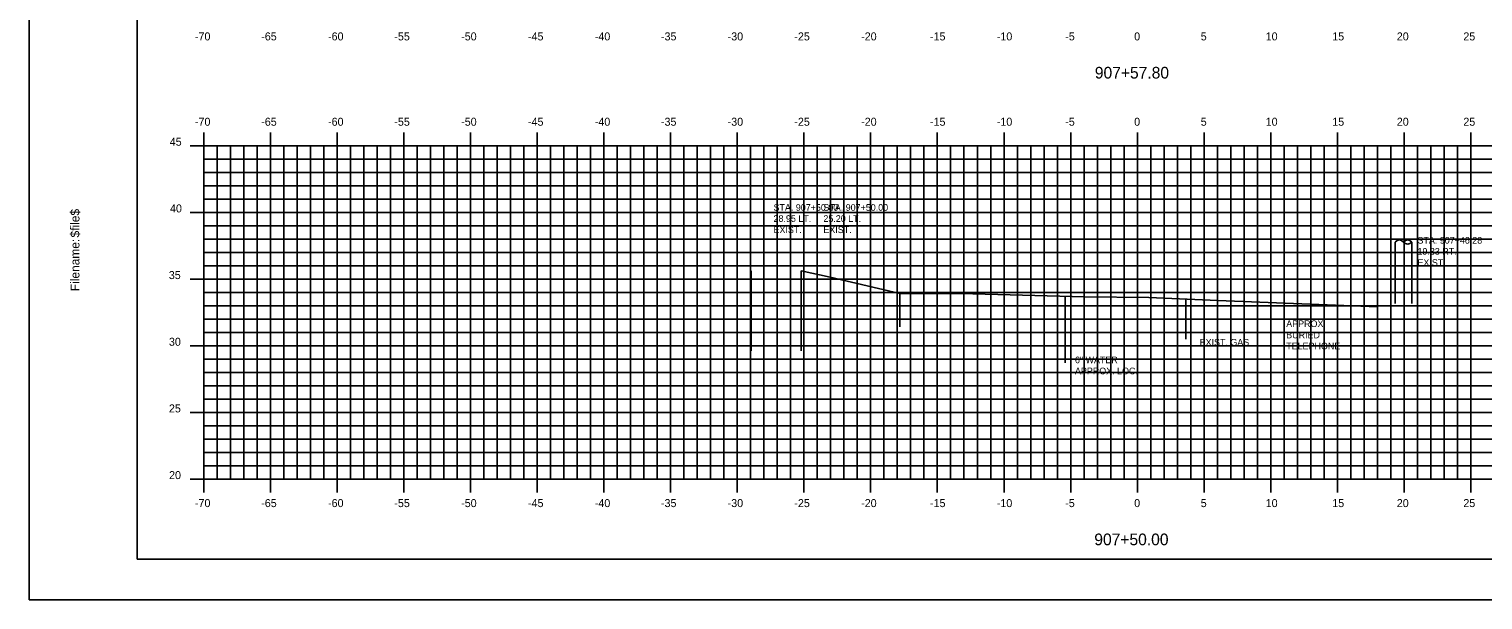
# Model space of a CAD drawing. Extents: x 1025909 to 1026079, y 394697 to 394807.
# Drawn here: x 1025908.6 to 1026017.6, y 394696.5 to 394739.4 of the extents above; entities that cross this region are included whole.
import ezdxf

# ---------------------------------------------------------------- set-up
doc = ezdxf.new("R2010")
doc.units = 0
for name, color, linetype in [('BORDER', 7, 'Continuous'), ('D_Text_Monospaced', 7, 'Continuous'), ('H_V ANNOTATION', 7, 'Continuous'), ('MAJOR', 7, 'Continuous'), ('MINOR', 7, 'Continuous'), ('PLOT BOUNDARY', 7, 'Continuous'), ('S_Roadway_Centerline', 7, 'Continuous'), ('S_Roadway_Edge_Pavement', 7, 'Continuous'), ('S_Utilities_Pole_Power', 7, 'Continuous'), ('S_Utilities_UG_Gas_Line', 7, 'Continuous'), ('S_Utilities_UG_Sanitary_Sewer', 7, 'Continuous'), ('S_Utilities_UG_Water_Line', 7, 'Continuous')]:
    doc.layers.add(name, color=color, linetype=linetype)

msp = doc.modelspace()

# ---------------------------------------------------------------- linework, layer by layer
at = {"layer": 'BORDER'}
for p, q in [((1025916.68, 394804.61), (1025916.68, 394699.61)), ((1025916.68, 394699.61), (1026076.68, 394699.61))]:
    msp.add_line(p, q, dxfattribs=at)
at = {"layer": 'MAJOR'}
for p, q in [((1025921.68, 394731.61), (1025921.68, 394730.61)), ((1025926.68, 394731.61), (1025926.68, 394730.61)), ((1025931.68, 394731.61), (1025931.68, 394730.61)), ((1025936.68, 394731.61), (1025936.68, 394730.61)), ((1025941.68, 394731.61), (1025941.68, 394730.61)), ((1025946.68, 394731.61), (1025946.68, 394730.61)), ((1025951.68, 394731.61), (1025951.68, 394730.61)), ((1025956.68, 394731.61), (1025956.68, 394730.61)), ((1025961.68, 394731.61), (1025961.68, 394730.61)), ((1025966.68, 394731.61), (1025966.68, 394730.61)), ((1025971.68, 394731.61), (1025971.68, 394730.61)), ((1025976.68, 394731.61), (1025976.68, 394730.61)), ((1025981.68, 394731.61), (1025981.68, 394730.61)), ((1025986.68, 394731.61), (1025986.68, 394730.61)), ((1025991.68, 394731.61), (1025991.68, 394730.61)), ((1025996.68, 394731.61), (1025996.68, 394730.61)), ((1026001.68, 394731.61), (1026001.68, 394730.61)), ((1026006.68, 394731.61), (1026006.68, 394730.61)), ((1026011.68, 394731.61), (1026011.68, 394730.61)), ((1026016.68, 394731.61), (1026016.68, 394730.61)), ((1025920.67, 394730.61), (1025921.68, 394730.61)), ((1025921.68, 394730.61), (1026061.68, 394730.61)), ((1025921.68, 394705.61), (1025921.68, 394730.61)), ((1025926.68, 394705.61), (1025926.68, 394730.61)), ((1025931.68, 394705.61), (1025931.68, 394730.61)), ((1025936.68, 394705.61), (1025936.68, 394730.61)), ((1025941.68, 394705.61), (1025941.68, 394730.61)), ((1025946.68, 394705.61), (1025946.68, 394730.61)), ((1025951.68, 394705.61), (1025951.68, 394730.61)), ((1025956.68, 394705.61), (1025956.68, 394730.61)), ((1025961.68, 394705.61), (1025961.68, 394730.61)), ((1025966.68, 394705.61), (1025966.68, 394730.61)), ((1025971.68, 394705.61), (1025971.68, 394730.61)), ((1025976.68, 394705.61), (1025976.68, 394730.61)), ((1025981.68, 394705.61), (1025981.68, 394730.61)), ((1025986.68, 394705.61), (1025986.68, 394730.61)), ((1025991.68, 394705.61), (1025991.68, 394730.61)), ((1025996.68, 394705.61), (1025996.68, 394730.61)), ((1026001.68, 394705.61), (1026001.68, 394730.61)), ((1026006.68, 394705.61), (1026006.68, 394730.61)), ((1026011.68, 394705.61), (1026011.68, 394730.61)), ((1026016.68, 394705.61), (1026016.68, 394730.61)), ((1025920.67, 394725.61), (1025921.68, 394725.61)), ((1025921.68, 394725.61), (1026061.68, 394725.61)), ((1025920.67, 394720.61), (1025921.68, 394720.61)), ((1025921.68, 394720.61), (1026061.68, 394720.61)), ((1025920.67, 394715.61), (1025921.68, 394715.61)), ((1025921.68, 394715.61), (1026061.68, 394715.61)), ((1025920.67, 394710.61), (1025921.68, 394710.61)), ((1025921.68, 394710.61), (1026061.68, 394710.61)), ((1025920.67, 394705.61), (1025921.68, 394705.61)), ((1025921.68, 394705.61), (1026061.68, 394705.61)), ((1025921.68, 394704.6), (1025921.68, 394705.61)), ((1025926.68, 394704.6), (1025926.68, 394705.61)), ((1025931.68, 394704.6), (1025931.68, 394705.61)), ((1025936.68, 394704.6), (1025936.68, 394705.61)), ((1025941.68, 394704.6), (1025941.68, 394705.61)), ((1025946.68, 394704.6), (1025946.68, 394705.61)), ((1025951.68, 394704.6), (1025951.68, 394705.61)), ((1025956.68, 394704.6), (1025956.68, 394705.61)), ((1025961.68, 394704.6), (1025961.68, 394705.61)), ((1025966.68, 394704.6), (1025966.68, 394705.61)), ((1025971.68, 394704.6), (1025971.68, 394705.61)), ((1025976.68, 394704.6), (1025976.68, 394705.61)), ((1025981.68, 394704.6), (1025981.68, 394705.61)), ((1025986.68, 394704.6), (1025986.68, 394705.61)), ((1025991.68, 394704.6), (1025991.68, 394705.61)), ((1025996.68, 394704.6), (1025996.68, 394705.61)), ((1026001.68, 394704.6), (1026001.68, 394705.61)), ((1026006.68, 394704.6), (1026006.68, 394705.61)), ((1026011.68, 394704.6), (1026011.68, 394705.61)), ((1026016.68, 394704.6), (1026016.68, 394705.61))]:
    msp.add_line(p, q, dxfattribs=at)
at = {"layer": 'MINOR'}
for p, q in [((1025922.68, 394705.61), (1025922.68, 394730.61)), ((1025923.68, 394705.61), (1025923.68, 394730.61)), ((1025924.68, 394705.61), (1025924.68, 394730.61)), ((1025925.68, 394705.61), (1025925.68, 394730.61)), ((1025927.68, 394705.61), (1025927.68, 394730.61)), ((1025928.68, 394705.61), (1025928.68, 394730.61)), ((1025929.68, 394705.61), (1025929.68, 394730.61)), ((1025930.68, 394705.61), (1025930.68, 394730.61)), ((1025932.68, 394705.61), (1025932.68, 394730.61)), ((1025933.68, 394705.61), (1025933.68, 394730.61)), ((1025934.68, 394705.61), (1025934.68, 394730.61)), ((1025935.68, 394705.61), (1025935.68, 394730.61)), ((1025937.68, 394705.61), (1025937.68, 394730.61)), ((1025938.68, 394705.61), (1025938.68, 394730.61)), ((1025939.68, 394705.61), (1025939.68, 394730.61)), ((1025940.68, 394705.61), (1025940.68, 394730.61)), ((1025942.68, 394705.61), (1025942.68, 394730.61)), ((1025943.68, 394705.61), (1025943.68, 394730.61)), ((1025944.68, 394705.61), (1025944.68, 394730.61)), ((1025945.68, 394705.61), (1025945.68, 394730.61)), ((1025947.68, 394705.61), (1025947.68, 394730.61)), ((1025948.68, 394705.61), (1025948.68, 394730.61)), ((1025949.68, 394705.61), (1025949.68, 394730.61)), ((1025950.68, 394705.61), (1025950.68, 394730.61)), ((1025952.68, 394705.61), (1025952.68, 394730.61)), ((1025953.68, 394705.61), (1025953.68, 394730.61)), ((1025954.68, 394705.61), (1025954.68, 394730.61)), ((1025955.68, 394705.61), (1025955.68, 394730.61)), ((1025957.68, 394705.61), (1025957.68, 394730.61)), ((1025958.68, 394705.61), (1025958.68, 394730.61)), ((1025959.68, 394705.61), (1025959.68, 394730.61)), ((1025960.68, 394705.61), (1025960.68, 394730.61)), ((1025962.68, 394705.61), (1025962.68, 394730.61)), ((1025963.68, 394705.61), (1025963.68, 394730.61)), ((1025964.68, 394705.61), (1025964.68, 394730.61)), ((1025965.68, 394705.61), (1025965.68, 394730.61)), ((1025967.68, 394705.61), (1025967.68, 394730.61)), ((1025968.68, 394705.61), (1025968.68, 394730.61)), ((1025969.68, 394705.61), (1025969.68, 394730.61)), ((1025970.68, 394705.61), (1025970.68, 394730.61)), ((1025972.68, 394705.61), (1025972.68, 394730.61)), ((1025973.68, 394705.61), (1025973.68, 394730.61)), ((1025974.68, 394705.61), (1025974.68, 394730.61)), ((1025975.68, 394705.61), (1025975.68, 394730.61)), ((1025977.68, 394705.61), (1025977.68, 394730.61)), ((1025978.68, 394705.61), (1025978.68, 394730.61)), ((1025979.68, 394705.61), (1025979.68, 394730.61)), ((1025980.68, 394705.61), (1025980.68, 394730.61)), ((1025982.68, 394705.61), (1025982.68, 394730.61)), ((1025983.68, 394705.61), (1025983.68, 394730.61)), ((1025984.68, 394705.61), (1025984.68, 394730.61)), ((1025985.68, 394705.61), (1025985.68, 394730.61)), ((1025987.68, 394705.61), (1025987.68, 394730.61)), ((1025988.68, 394705.61), (1025988.68, 394730.61)), ((1025989.68, 394705.61), (1025989.68, 394730.61)), ((1025990.68, 394705.61), (1025990.68, 394730.61)), ((1025992.68, 394705.61), (1025992.68, 394730.61)), ((1025993.68, 394705.61), (1025993.68, 394730.61)), ((1025994.68, 394705.61), (1025994.68, 394730.61)), ((1025995.68, 394705.61), (1025995.68, 394730.61)), ((1025997.68, 394705.61), (1025997.68, 394730.61)), ((1025998.68, 394705.61), (1025998.68, 394730.61)), ((1025999.68, 394705.61), (1025999.68, 394730.61)), ((1026000.68, 394705.61), (1026000.68, 394730.61)), ((1026002.68, 394705.61), (1026002.68, 394730.61)), ((1026003.68, 394705.61), (1026003.68, 394730.61)), ((1026004.68, 394705.61), (1026004.68, 394730.61)), ((1026005.68, 394705.61), (1026005.68, 394730.61)), ((1026007.68, 394705.61), (1026007.68, 394730.61)), ((1026008.68, 394705.61), (1026008.68, 394730.61)), ((1026009.68, 394705.61), (1026009.68, 394730.61)), ((1026010.68, 394705.61), (1026010.68, 394730.61)), ((1026012.68, 394705.61), (1026012.68, 394730.61)), ((1026013.68, 394705.61), (1026013.68, 394730.61)), ((1026014.68, 394705.61), (1026014.68, 394730.61)), ((1026015.68, 394705.61), (1026015.68, 394730.61)), ((1025921.68, 394729.61), (1026061.68, 394729.61)), ((1025921.68, 394729.61), (1025922.68, 394729.61)), ((1025921.68, 394728.61), (1026061.68, 394728.61)), ((1025921.68, 394728.61), (1025922.68, 394728.61)), ((1025921.68, 394727.61), (1026061.68, 394727.61)), ((1025921.68, 394727.61), (1025922.68, 394727.61)), ((1025921.68, 394726.61), (1026061.68, 394726.61)), ((1025921.68, 394726.61), (1025922.68, 394726.61)), ((1025921.68, 394724.61), (1026061.68, 394724.61)), ((1025921.68, 394724.61), (1025922.68, 394724.61)), ((1025921.68, 394723.61), (1026061.68, 394723.61)), ((1025921.68, 394723.61), (1025922.68, 394723.61)), ((1025921.68, 394722.61), (1026061.68, 394722.61)), ((1025921.68, 394722.61), (1025922.68, 394722.61)), ((1025921.68, 394721.61), (1026061.68, 394721.61)), ((1025921.68, 394721.61), (1025922.68, 394721.61)), ((1025921.68, 394719.61), (1026061.68, 394719.61)), ((1025921.68, 394719.61), (1025922.68, 394719.61)), ((1025921.68, 394718.61), (1026061.68, 394718.61)), ((1025921.68, 394718.61), (1025922.68, 394718.61)), ((1025921.68, 394717.61), (1026061.68, 394717.61)), ((1025921.68, 394717.61), (1025922.68, 394717.61)), ((1025921.68, 394716.61), (1026061.68, 394716.61)), ((1025921.68, 394716.61), (1025922.68, 394716.61)), ((1025921.68, 394714.61), (1026061.68, 394714.61)), ((1025921.68, 394714.61), (1025922.68, 394714.61)), ((1025921.68, 394713.61), (1026061.68, 394713.61)), ((1025921.68, 394713.61), (1025922.68, 394713.61)), ((1025921.68, 394712.61), (1026061.68, 394712.61)), ((1025921.68, 394712.61), (1025922.68, 394712.61)), ((1025921.68, 394711.61), (1026061.68, 394711.61)), ((1025921.68, 394711.61), (1025922.68, 394711.61)), ((1025921.68, 394709.61), (1026061.68, 394709.61)), ((1025921.68, 394709.61), (1025922.68, 394709.61)), ((1025921.68, 394708.61), (1026061.68, 394708.61)), ((1025921.68, 394708.61), (1025922.68, 394708.61)), ((1025921.68, 394707.61), (1026061.68, 394707.61)), ((1025921.68, 394707.61), (1025922.68, 394707.61)), ((1025921.68, 394706.61), (1026061.68, 394706.61)), ((1025921.68, 394706.61), (1025922.68, 394706.61))]:
    msp.add_line(p, q, dxfattribs=at)
at = {"layer": 'PLOT BOUNDARY'}
msp.add_lwpolyline([(1025908.58, 394696.55), (1026078.58, 394696.55), (1026078.58, 394806.55), (1025908.58, 394806.55)], close=True, dxfattribs=at)
at = {"layer": 'S_Roadway_Centerline'}
msp.add_lwpolyline([(1025966.48, 394721.23), (1025968.64, 394720.76), (1025973.86, 394719.52), (1025978.41, 394719.52), (1025987.71, 394719.28), (1025992.53, 394719.24), (1025997.71, 394719), (1026009.68, 394718.52)], dxfattribs=at)
at = {"layer": 'S_Roadway_Edge_Pavement'}
for p, q in [((1025973.86, 394719.52), (1025973.86, 394717.02)), ((1026009.68, 394718.52), (1026009.68, 394716.02))]:
    msp.add_line(p, q, dxfattribs=at)
at = {"layer": 'S_Utilities_Pole_Power'}
for p, q in [((1026011.01, 394723.39), (1026011.16, 394723.5)), ((1026011.01, 394718.77), (1026011.01, 394723.39)), ((1026011.48, 394723.5), (1026011.63, 394723.39)), ((1026011.79, 394723.5), (1026011.63, 394723.39)), ((1026011.63, 394723.39), (1026011.79, 394723.28)), ((1026012.26, 394723.39), (1026012.1, 394723.5)), ((1026012.1, 394723.28), (1026012.26, 394723.39)), ((1026012.26, 394718.77), (1026012.26, 394723.39))]:
    msp.add_line(p, q, dxfattribs=at)
for centre, start, end in [((1026011.32, 394723.28), 90, 125.2644), ((1026011.32, 394723.28), 54.7356, 90), ((1026011.95, 394723.28), 90, 125.2644), ((1026011.95, 394723.5), 234.7356, 270), ((1026011.95, 394723.28), 54.7356, 90), ((1026011.95, 394723.5), 270, 305.2644)]:
    msp.add_arc(centre, 0.271, start, end, dxfattribs=at)
at = {"layer": 'S_Utilities_UG_Gas_Line'}
msp.add_line((1025995.31, 394719.11), (1025995.31, 394716.11), dxfattribs=at)
at = {"layer": 'S_Utilities_UG_Sanitary_Sewer'}
for p, q in [((1025962.73, 394721.23), (1025962.73, 394715.23)), ((1025966.48, 394721.23), (1025966.48, 394715.23))]:
    msp.add_line(p, q, dxfattribs=at)
at = {"layer": 'S_Utilities_UG_Water_Line'}
for p, q in [((1025986.26, 394719.32), (1025986.26, 394714.32)), ((1026001.68, 394718.84), (1026001.68, 394715.79))]:
    msp.add_line(p, q, dxfattribs=at)

# ---------------------------------------------------------------- texts
at = {"layer": 'BORDER'}
for s, p in [('$file$', (1025912.36, 394723.73)), ('Filename:', (1025912.36, 394719.7))]:
    msp.add_text(s, height=0.67, rotation=90, dxfattribs=at).set_placement(p)
at = {"layer": 'D_Text_Monospaced'}
for s, p in [('STA. 907+50.00', (1025964.4, 394725.73)), ('28.95 LT.', (1025964.4, 394724.9)), ('STA. 907+50.00', (1025968.14, 394725.73)), ('25.20 LT.', (1025968.14, 394724.9)), ('EXIST. ', (1025964.4, 394724.06)), ('EXIST. ', (1025968.14, 394724.06)), ('STA. 907+46.28', (1026012.68, 394723.27)), ('19.33 RT.', (1026012.68, 394722.44)), ('EXIST. ', (1026012.68, 394721.6)), ('APPROX', (1026002.84, 394717.01)), ('BURIED ', (1026002.84, 394716.17)), ('EXIST. GAS', (1025996.35, 394715.62)), ('TELEPHONE', (1026002.84, 394715.34)), ('6" WATER', (1025987, 394714.3)), ('APPROX. LOC.', (1025987, 394713.47))]:
    msp.add_text(s, height=0.5, dxfattribs=at).set_placement(p)
at = {"layer": 'H_V ANNOTATION'}
for s, height, p in [('-70', 0.6, (1025921.02, 394738.51)), ('-65', 0.6, (1025925.99, 394738.51)), ('-60', 0.6, (1025931, 394738.51)), ('-55', 0.6, (1025935.97, 394738.51)), ('-50', 0.6, (1025940.98, 394738.51)), ('-45', 0.6, (1025945.99, 394738.51)), ('-40', 0.6, (1025951, 394738.51)), ('-35', 0.6, (1025955.96, 394738.51)), ('-30', 0.6, (1025960.96, 394738.51)), ('-25', 0.6, (1025965.96, 394738.51)), ('-20', 0.6, (1025970.97, 394738.51)), ('-15', 0.6, (1025976.13, 394738.51)), ('-10', 0.6, (1025981.14, 394738.51)), ('-5', 0.6, (1025986.27, 394738.51)), ('0', 0.6, (1025991.44, 394738.51)), ('5', 0.6, (1025996.43, 394738.51)), ('10', 0.6, (1026001.3, 394738.51)), ('15', 0.6, (1026006.29, 394738.51)), ('20', 0.6, (1026011.13, 394738.51)), ('25', 0.6, (1026016.12, 394738.51)), ('907+57.80', 0.875, (1025988.49, 394735.65)), ('-70', 0.6, (1025921.02, 394732.11)), ('-65', 0.6, (1025925.99, 394732.11)), ('-60', 0.6, (1025931, 394732.11)), ('-55', 0.6, (1025935.97, 394732.11)), ('-50', 0.6, (1025940.98, 394732.11)), ('-45', 0.6, (1025945.99, 394732.11)), ('-40', 0.6, (1025951, 394732.11)), ('-35', 0.6, (1025955.96, 394732.11)), ('-30', 0.6, (1025960.96, 394732.11)), ('-25', 0.6, (1025965.96, 394732.11)), ('-20', 0.6, (1025970.97, 394732.11)), ('-15', 0.6, (1025976.13, 394732.11)), ('-10', 0.6, (1025981.14, 394732.11)), ('-5', 0.6, (1025986.27, 394732.11)), ('0', 0.6, (1025991.44, 394732.11)), ('5', 0.6, (1025996.43, 394732.11)), ('10', 0.6, (1026001.3, 394732.11)), ('15', 0.6, (1026006.29, 394732.11)), ('20', 0.6, (1026011.13, 394732.11)), ('25', 0.6, (1026016.12, 394732.11)), ('45', 0.6, (1025919.13, 394730.61)), ('40', 0.6, (1025919.15, 394725.61)), ('35', 0.6, (1025919.06, 394720.61)), ('30', 0.6, (1025919.07, 394715.61)), ('25', 0.6, (1025919.07, 394710.61)), ('20', 0.6, (1025919.08, 394705.61)), ('-70', 0.6, (1025921.02, 394703.51)), ('-65', 0.6, (1025925.99, 394703.51)), ('-60', 0.6, (1025931, 394703.51)), ('-55', 0.6, (1025935.97, 394703.51)), ('-50', 0.6, (1025940.98, 394703.51)), ('-45', 0.6, (1025945.99, 394703.51)), ('-40', 0.6, (1025951, 394703.51)), ('-35', 0.6, (1025955.96, 394703.51)), ('-30', 0.6, (1025960.96, 394703.51)), ('-25', 0.6, (1025965.96, 394703.51)), ('-20', 0.6, (1025970.97, 394703.51)), ('-15', 0.6, (1025976.13, 394703.51)), ('-10', 0.6, (1025981.14, 394703.51)), ('-5', 0.6, (1025986.27, 394703.51)), ('0', 0.6, (1025991.44, 394703.51)), ('5', 0.6, (1025996.43, 394703.51)), ('10', 0.6, (1026001.3, 394703.51)), ('15', 0.6, (1026006.29, 394703.51)), ('20', 0.6, (1026011.13, 394703.51)), ('25', 0.6, (1026016.12, 394703.51)), ('907+50.00', 0.875, (1025988.45, 394700.65))]:
    msp.add_text(s, height=height, dxfattribs=at).set_placement(p)
at = {"layer": 'S_Roadway_Centerline'}
for s in ['C', 'L']:
    msp.add_text(s, height=0.0146, dxfattribs=at).set_placement((1025992.53, 394719.24))

doc.saveas('drawing.dxf')
